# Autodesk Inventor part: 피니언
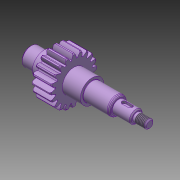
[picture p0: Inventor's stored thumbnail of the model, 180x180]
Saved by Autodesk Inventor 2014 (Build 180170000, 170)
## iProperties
Created: 2019-06
Part Number: 피니언
Material: 스테인리스강
Document SubType Name: Modeling
Designer: mduedu
Density: 1 g/cm^3
Appearance: 기본값(1)
Author: mduedu
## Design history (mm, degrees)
sketch "스케치1"
  geometry: L1 (0, 0)-(13, 0); L2 (13, 0)-(13, 8.5); L3 (13, 8.5)-(0, 8.5); L4 (0, 8.5)-(0, 0); L5 (13, 0)-(58, 0); L6 (58, 0)-(58, 11); L7 (58, 11)-(13, 11); L8 (13, 11)-(13, 0); L9 (58, 0)-(83, 0); L10 (83, 0)-(83, 8.5); L11 (83, 8.5)-(58, 8.5); L12 (58, 8.5)-(58, 0); L13 (83, 0)-(100, 0); L14 (100, 0)-(100, 6); L15 (100, 6)-(83, 6); L16 (83, 6)-(83, 0); L17 (100, 0)-(112, 0); L18 (112, 0)-(112, 4); L19 (112, 4)-(100, 4); L20 (100, 4)-(100, 0)
  constraints: 40 end point, 10 parallel, 5 horizontal, 5 perpendicular
  dimensions: "d0" = 112 distance between parallel lines of L18 L4; "d2" = 83 distance between parallel lines of L10 L4; "d3" = 45 distance of L6.end L7.end; "d4" = 25 distance of L10.end L11.end; "d5" = 17 distance of L14.end L15.end; "d6" = 8 diameter of L19 L17; "d7" = 12 diameter of L15 L13; "d8" = 17 diameter of L11 L9; "d9" = 22 diameter of L7 L5; "d10" = 17 diameter of L3 L1
revolve "회전1" sketch "스케치1" stored, may be unused: angle "d11" = 90 deg
node "작업 평면1"
sketch "스케치2"
  geometry: C1 r 17.5 at (0, 0); C2 r 20 at (0, 0); C3 r 22 at (0, 0); 1 further point
  constraints: 3 centre point, 3 coincident
  dimensions: "d13" = 40 diameter of C2; "d15" = 44 diameter of C3; "d16" = 35 diameter of C1
extrude "돌출1" join sketch "스케치2" distance "d17" = 18; taper "d18" = 0 deg
sketch "스케치3"
  geometry: L1 (0, 0)-(22, 0); L2 (0, 0)-(0, 22); L3 (0.57, 0)-(0.57, 22); L4 (1.57, 0)-(1.57, 22); L5 (2.07, 0)-(2.07, 22); A1 r 22 centre (0, 0) between (22, 0) and (0, 22) reference; A2 r 9.495 centre (-7.411, 16.856) between (2.07, 17.377) and (0.57, 22); A3 r 9.495 centre (7.411, 16.856) between (-0.57, 22) and (-2.07, 17.377); A4 r 17.5 centre (0, 0) between (2.07, 17.377) and (-2.07, 17.377); A5 r 22.007 centre (0, 0) between (0.57, 22) and (-0.57, 22); 4 further points
  constraints: 11 point on circle, 10 end point, 6 parallel, 5 point on line, 4 centre point, 3 symmetric about line, 2 coincident, 1 horizontal, 1 perpendicular, 5 other
  dimensions: "d19" = 0.5 distance between parallel lines of L5 L4; "d21" = 1 distance between parallel lines of L3 L4; "d22" = 1.57 distance between parallel lines of L2 L4
extrude "돌출2" join sketch "스케치3" stored distance "d23" = 18; taper "d24" = 0 deg
chamfer "모따기1" distance "d25" = 1; stored, may be unused: second distance "d26" = 2, angle "d27" = 45 deg
fillet "모깎기1" dims "d31" = 0.3
chamfer "모따기2" distance "d32" = 1; stored, may be unused: second distance "d33" = 2, angle "d34" = 45 deg
node "작업 평면2"
sketch "스케치4"
  geometry: L1 (3.5, -2)-(-2.5, -2); L2 (-2.5, 2)-(3.5, 2); L3 (8.5, 8.5)-(8.5, -8.5) reference; A1 r 2 centre (3.5, 0) between (3.5, -2) and (3.5, 2); A2 r 2 centre (-2.5, 0) between (-2.5, 2) and (-2.5, -2); 1 further point
  constraints: 4 end point, 4 point on circle, 4 tangent, 2 centre point, 1 horizontal, 1 horizontal alignment, 1 parallel
  dimensions: "d35" = 3 distance edge to line of A1 L3; "d36" = 10 dimension on A2 A1; "d37" = 4 distance between parallel lines of L2 L1
extrude "돌출3" cut sketch "스케치4" distance "d38" = 2.5; taper "d39" = 0 deg
chamfer "모따기3" distance "d40" = 1.82; stored, may be unused: second distance "d41" = 2, angle "d42" = 30 deg
fillet "모깎기2" dims "d43" = 1, "d44" = 2
chamfer "모따기4" distance "d45" = 1; stored, may be unused: second distance "d46" = 2, angle "d47" = 30 deg
feature "스레드1" dims "d48" = 10, "d49" = 0
chamfer "모따기5" distance "d50" = 1; stored, may be unused: second distance "d51" = 2, angle "d52" = 30 deg
node "솔리드1"
pattern_circular "원형 패턴1" dims angle "d29" = 360 deg
other parameters: "d12" = -17
